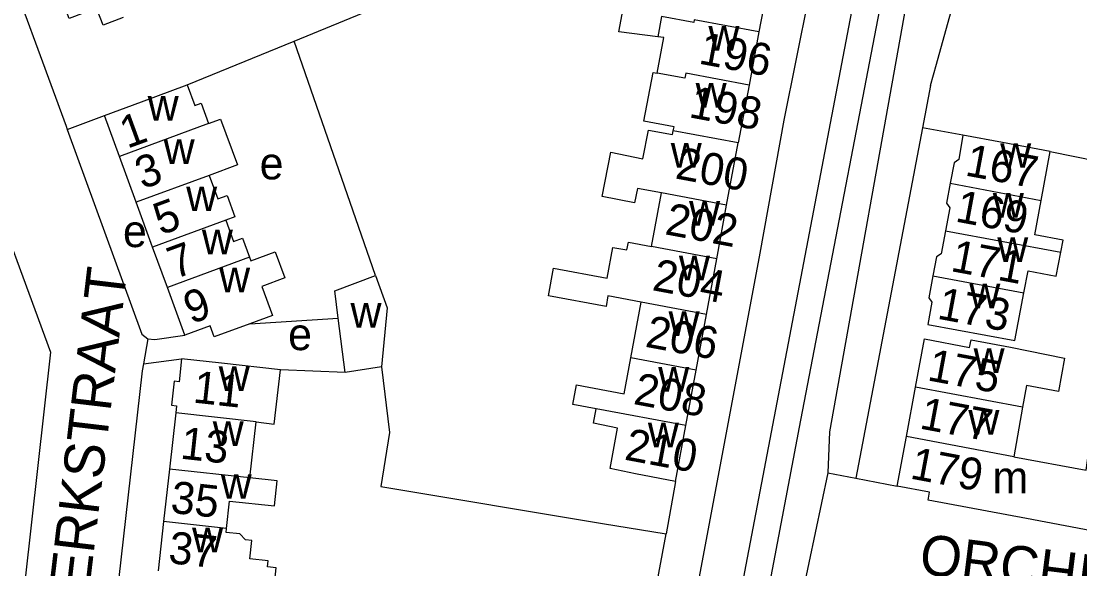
# Model space of a CAD drawing. Extents: x 161258 to 163262, y 380749 to 382054.
# Drawn here: x 161707.1 to 161839.1, y 381411.8 to 381480.1 of the extents above; entities that cross this region are included whole.
import ezdxf

# ---------------------------------------------------------------- set-up
doc = ezdxf.new("R2010")
doc.units = 0
for name, color, linetype in [('BLT_Basislijn', 7, 'Continuous'), ('BLT_Bebouwing', 7, 'Continuous'), ('BLT_Centroide', 7, 'Continuous'), ('BLT_Huisnummer', 7, 'Continuous'), ('BLT_Huisnummer_ tussenligend', 7, 'Continuous'), ('BLT_Onderdoorgang_en_onderverdeling', 7, 'Continuous'), ('BLT_Onderverdeling_panden', 7, 'Continuous'), ('BLT_Straatnaam', 7, 'Continuous'), ('BLT_Vlakafsluiter', 7, 'Continuous')]:
    doc.layers.add(name, color=color, linetype=linetype)

msp = doc.modelspace()

# ---------------------------------------------------------------- linework, layer by layer
at = {"layer": 'BLT_Basislijn'}
for p, q in [((161813.65, 381524.97), (161802.19, 381467.74)), ((161741.1, 381477.58), (161749.72, 381481.11)), ((161727.79, 381472.14), (161741.1, 381477.58)), ((161751.25, 381448.4), (161741.1, 381477.58)), ((161820.46, 381472.07), (161821.19, 381474.73)), ((161820.46, 381472.07), (161819.46, 381466.81)), ((161712.83, 381466.59), (161717.45, 381468.35)), ((161802.19, 381467.74), (161799.16, 381451.16)), ((161712.83, 381466.59), (161722.12, 381441.07)), ((161819.46, 381466.81), (161811.16, 381423.12)), ((161824.51, 381465.87), (161819.46, 381466.81)), ((161799.16, 381451.16), (161778.91, 381343.24)), ((161735.6, 381442.38), (161746.61, 381443.09)), ((161722.12, 381441.07), (161722.85, 381440.5)), ((161723.74, 381440.42), (161727.49, 381440.96)), ((161722.85, 381440.5), (161722.33, 381437.39)), ((161722.85, 381440.5), (161723.74, 381440.42)), ((161722.33, 381437.39), (161727.07, 381438)), ((161747.49, 381436.31), (161739.42, 381436.63)), ((161807.65, 381423.81), (161811.16, 381423.12)), ((161788.65, 381422.73), (161787.5, 381416.19)), ((161811.16, 381423.12), (161816.29, 381422.13)), ((161773.35, 381339.87), (161787.5, 381416.19))]:
    msp.add_line(p, q, dxfattribs=at)
for points in [[(161787.91, 381344.08), (161804.27, 381430.36), (161834.23, 381585.88), (161842.37, 381628.14)], [(161784.66, 381344.68), (161797.46, 381412.33), (161836.25, 381615.34)], [(161821.19, 381474.73), (161830.92, 381509.79), (161840.57, 381561.92)], [(161735.27, 381503.44), (161734.11, 381503.59), (161724.44, 381500), (161704.01, 381491.08), (161703.96, 381490.64), (161712.68, 381466.99), (161712.83, 381466.59)], [(161817.65, 381483.44), (161807.85, 381428.9), (161807.65, 381423.81)], [(161835.39, 381463.83), (161850.14, 381460.87), (161847.56, 381441.93)], [(161701.85, 381462.93), (161710.73, 381438.82), (161706.75, 381403.16)], [(161722.33, 381437.39), (161722.18, 381436.49), (161718.64, 381405.21), (161712.26, 381347.41), (161773.35, 381339.87)], [(161752.01, 381437), (161753.01, 381428.81), (161751.94, 381422.09), (161779.58, 381417.49), (161787.5, 381416.19)]]:
    msp.add_lwpolyline(points, dxfattribs=at)
at = {"layer": 'BLT_Bebouwing'}
for p, q in [((161800.42, 381486.02), (161799.06, 381478.75)), ((161799.06, 381478.75), (161797.83, 381472.13)), ((161727.79, 381472.14), (161728.72, 381469.59)), ((161797.83, 381472.13), (161796.48, 381464.92)), ((161719.32, 381463.24), (161717.45, 381468.35)), ((161795.04, 381457.16), (161796.48, 381464.92)), ((161721.42, 381457.53), (161719.32, 381463.24)), ((161785.68, 381452), (161786.93, 381458.68)), ((161723.47, 381451.93), (161721.42, 381457.53)), ((161793.8, 381450.48), (161795.04, 381457.16)), ((161725.31, 381446.91), (161723.47, 381451.93)), ((161792.51, 381443.54), (161793.8, 381450.48)), ((161727.49, 381440.96), (161725.31, 381446.91)), ((161783.09, 381438.14), (161784.38, 381445.07)), ((161791.23, 381436.61), (161792.51, 381443.54)), ((161747.49, 381436.31), (161746.61, 381443.09)), ((161818.6, 381434.48), (161819.73, 381440.49)), ((161782.25, 381433.66), (161783.09, 381438.14)), ((161752.01, 381437), (161747.49, 381436.31)), ((161789.94, 381429.68), (161791.23, 381436.61)), ((161817.45, 381428.32), (161818.6, 381434.48)), ((161726.36, 381431.29), (161725.56, 381424.27)), ((161735.6, 381423.16), (161736.37, 381430.14)), ((161788.65, 381422.73), (161789.94, 381429.68)), ((161816.29, 381422.13), (161817.45, 381428.32)), ((161725.56, 381424.27), (161724.84, 381417.73)), ((161844.72, 381415.79), (161832.44, 381418.09)), ((161724.84, 381417.73), (161724.17, 381411.6))]:
    msp.add_line(p, q, dxfattribs=at)
for points in [[(161719.81, 381480.54), (161717.28, 381479.59), (161716.48, 381481.71), (161713.08, 381480.43), (161710.21, 381488.02), (161716.14, 381490.25)], [(161786.47, 381478.15), (161781.6, 381478.77), (161782.14, 381481.62), (161786.26, 381481.09), (161787.31, 381486.67)], [(161786.38, 381473.61), (161787.21, 381478.06), (161786.47, 381478.15)], [(161788.38, 381466.44), (161788.49, 381466.93), (161784.72, 381467.63), (161785.86, 381473.71), (161786.38, 381473.61)], [(161717.45, 381468.35), (161722.1, 381470.05), (161727.79, 381472.14)], [(161728.72, 381469.59), (161729.51, 381469.88), (161730.45, 381467.32)], [(161730.45, 381467.32), (161731.95, 381467.88), (161734.05, 381462.19), (161730.52, 381460.87)], [(161786.93, 381458.68), (161783.92, 381459.24), (161783.55, 381457.43), (161779.51, 381458.25), (161780.62, 381463.76), (161784.61, 381462.95), (161785.28, 381466.51), (161788.28, 381465.95), (161788.38, 381466.44)], [(161824.51, 381465.87), (161823.98, 381462.85), (161823.4, 381462.45), (161822.92, 381459.89)], [(161835.39, 381463.83), (161829.43, 381464.95), (161824.51, 381465.87)], [(161834.27, 381457.74), (161835.39, 381463.83)], [(161730.52, 381460.87), (161731.59, 381457.95), (161732.75, 381458.37), (161733.73, 381455.69), (161732.6, 381455.28)], [(161822.92, 381459.89), (161822.45, 381457.4), (161822.85, 381456.83), (161822.31, 381453.96)], [(161836.7, 381451.28), (161836.99, 381452.78), (161833.46, 381453.45), (161834.27, 381457.74)], [(161732.6, 381455.28), (161733.57, 381452.64), (161734.69, 381453.05), (161735.56, 381450.67)], [(161822.31, 381453.96), (161821.77, 381451.09), (161821.19, 381450.7), (161820.75, 381448.34)], [(161784.38, 381445.07), (161780.24, 381445.85), (161780.03, 381444.51), (161772.82, 381445.86), (161773.47, 381449.31), (161780.14, 381448.06), (161780.86, 381451.89), (161782.59, 381451.57), (161782.79, 381452.54), (161785.68, 381452)], [(161735.56, 381450.67), (161735.72, 381450.23), (161738.76, 381451.34), (161739.95, 381448.08), (161737.08, 381447.03), (161738.4, 381443.41), (161735.6, 381442.38)], [(161832.1, 381446.23), (161832.62, 381448.97), (161836.14, 381448.3), (161836.7, 381451.28)], [(161746.61, 381443.09), (161746.17, 381446.47), (161751.25, 381448.4)], [(161751.25, 381448.4), (161752.71, 381444.36), (161752.01, 381437)], [(161820.75, 381448.34), (161820.24, 381445.62), (161820.64, 381445.05), (161820.12, 381442.3)], [(161820.12, 381442.3), (161830.98, 381440.27), (161832.1, 381446.23)], [(161735.6, 381442.38), (161731.13, 381440.75), (161730.63, 381442.11), (161727.49, 381440.96)], [(161819.73, 381440.49), (161825.34, 381439.43), (161825.51, 381440.36), (161830.43, 381439.44), (161837.17, 381438.08), (161836.4, 381433.93), (161832.42, 381434.67), (161831.92, 381431.99)], [(161727.07, 381438), (161726.78, 381435.15), (161726.17, 381435.22), (161725.84, 381432.22), (161726.46, 381432.16), (161726.36, 381431.29)], [(161739.42, 381436.63), (161732.06, 381437.45), (161727.07, 381438)], [(161736.37, 381430.14), (161738.64, 381429.88), (161739.42, 381436.63)], [(161778.77, 381431.76), (161775.85, 381432.31), (161776.31, 381434.77), (161782.25, 381433.66)], [(161788.65, 381422.73), (161783.69, 381423.67), (161780.51, 381424.32), (161781.45, 381429.37), (161778.44, 381429.97), (161778.77, 381431.76)], [(161831.92, 381431.99), (161830.84, 381425.81)], [(161830.84, 381425.81), (161839.87, 381424.12), (161840.71, 381430.16), (161846.39, 381428.98)], [(161732.68, 381416.87), (161733.06, 381420.28), (161738.66, 381419.67), (161739, 381422.79), (161735.6, 381423.16)], [(161832.44, 381418.09), (161820.17, 381420.38), (161820.35, 381421.37), (161816.29, 381422.13)], [(161738.67, 381410.01), (161738.88, 381411.95), (161737.8, 381412.07), (161737.88, 381412.84), (161735.57, 381413.1), (161735.82, 381415.35), (161735.03, 381415.44), (161734.36, 381416.18), (161732.63, 381416.37), (161732.68, 381416.87)]]:
    msp.add_lwpolyline(points, dxfattribs=at)
at = {"layer": 'BLT_Onderdoorgang_en_onderverdeling'}
msp.add_lwpolyline([(161796.48, 381464.92), (161788.38, 381466.44)], dxfattribs=at)
at = {"layer": 'BLT_Onderverdeling_panden'}
for p, q in [((161730.45, 381467.32), (161719.32, 381463.24)), ((161730.52, 381460.87), (161721.42, 381457.53)), ((161822.92, 381459.89), (161834.27, 381457.74)), ((161795.04, 381457.16), (161786.93, 381458.68)), ((161732.6, 381455.28), (161723.47, 381451.93)), ((161822.31, 381453.96), (161836.7, 381451.28)), ((161793.8, 381450.48), (161785.68, 381452)), ((161735.56, 381450.67), (161725.31, 381446.91)), ((161820.75, 381448.34), (161832.1, 381446.23)), ((161792.51, 381443.54), (161784.38, 381445.07)), ((161791.23, 381436.61), (161783.09, 381438.14)), ((161831.92, 381431.99), (161818.6, 381434.48)), ((161736.37, 381430.14), (161726.36, 381431.29)), ((161789.94, 381429.68), (161778.77, 381431.76)), ((161830.84, 381425.81), (161817.45, 381428.32)), ((161735.6, 381423.16), (161725.56, 381424.27)), ((161732.68, 381416.87), (161724.84, 381417.73))]:
    msp.add_line(p, q, dxfattribs=at)
for points in [[(161799.06, 381478.75), (161791.01, 381480.25), (161790.95, 381479.93), (161786.93, 381480.67), (161786.47, 381478.15)], [(161797.83, 381472.13), (161789.95, 381473.6), (161789.83, 381472.97), (161786.38, 381473.61)]]:
    msp.add_lwpolyline(points, dxfattribs=at)
at = {"layer": 'BLT_Vlakafsluiter'}
msp.add_line((161807.65, 381423.81), (161804.31, 381407.91), dxfattribs=at)

# ---------------------------------------------------------------- texts
at = {"layer": 'BLT_Centroide'}
for s, p in [('w', (161792.77, 381476.41)), ('w', (161791.17, 381469.31)), ('w', (161722.85, 381467.69)), ('w', (161724.84, 381462.28)), ('w', (161788.07, 381461.84)), ('w', (161829.15, 381461.81)), ('e', (161736.81, 381460.37)), ('w', (161727.65, 381456.41)), ('w', (161828.23, 381455.59)), ('w', (161790.36, 381454.59)), ('e', (161719.77, 381451.93)), ('w', (161729.61, 381451.03)), ('w', (161828.78, 381450.09)), ('w', (161789.09, 381447.78)), ('w', (161731.76, 381446.31)), ('w', (161825.3, 381444.31)), ('w', (161748.14, 381441.89)), ('w', (161787.8, 381440.84)), ('e', (161740.36, 381439.09)), ('w', (161825.83, 381436.25)), ('w', (161731.71, 381434)), ('w', (161786.51, 381433.91)), ('w', (161825.18, 381428.54)), ('w', (161730.96, 381427.16)), ('w', (161785.22, 381426.97)), ('w', (161731.96, 381420.56)), ('m', (161828.19, 381421.24)), ('w', (161728.39, 381413.88))]:
    msp.add_text(s, height=4, dxfattribs=at).set_placement(p)
at = {"layer": 'BLT_Huisnummer'}
for s, rotation, p in [('196', 349.3846, (161791.43, 381474.82)), ('1', 20.1104, (161720.3, 381464.17)), ('200', 349.3846, (161788.51, 381460.51)), ('167', 349.4004, (161824.65, 381460.88)), ('5', 20.1134, (161724.48, 381453.37)), ('171', 349.4007, (161822.85, 381448.96)), ('204', 349.3846, (161785.64, 381446.58)), ('9', 20.1273, (161728.26, 381442.3)), ('175', 349.3956, (161819.94, 381435.35)), ('11', 353.7352, (161728.41, 381432.57)), ('13', 353.7342, (161726.82, 381425.58)), ('210', 349.3846, (161782.18, 381425.46)), ('179', 349.3889, (161817.79, 381423.11)), ('35', 353.7422, (161725.6, 381418.83))]:
    msp.add_text(s, height=4, rotation=rotation, dxfattribs=at).set_placement(p)
at = {"layer": 'BLT_Huisnummer_ tussenligend'}
for s, rotation, p in [('198', 349.3846, (161790.21, 381468.13)), ('3', 20.1104, (161722.2, 381459.1)), ('169', 349.4004, (161823.43, 381455.14)), ('202', 349.3846, (161787.22, 381453.55)), ('7', 20.1134, (161726.24, 381447.91)), ('173', 349.4007, (161821.18, 381443.03)), ('206', 349.3846, (161784.77, 381439.53)), ('208', 349.3846, (161783.3, 381432.39)), ('177', 349.3956, (161818.97, 381429.34)), ('37', 353.7422, (161725.33, 381412.56))]:
    msp.add_text(s, height=4, rotation=rotation, dxfattribs=at).set_placement(p)
at = {"layer": 'BLT_Straatnaam'}
for s, rotation, p in [('JACQUES PERKSTRAAT', 83.2287, (161711.11, 381371.59)), ('ORCHIDEEENSTRAAT', 352.8191, (161818.91, 381411.26))]:
    msp.add_text(s, height=5, rotation=rotation, dxfattribs=at).set_placement(p)

doc.saveas('drawing.dxf')
